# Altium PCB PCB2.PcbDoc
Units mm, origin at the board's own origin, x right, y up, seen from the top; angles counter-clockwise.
Board outline 26.92 x 36.58 mm, 2 copper layers (Top Layer, Bottom Layer); 10 components, 8 nets, 35 pads, 0 vias.
Unrouted connection lines stored in the file: 2.
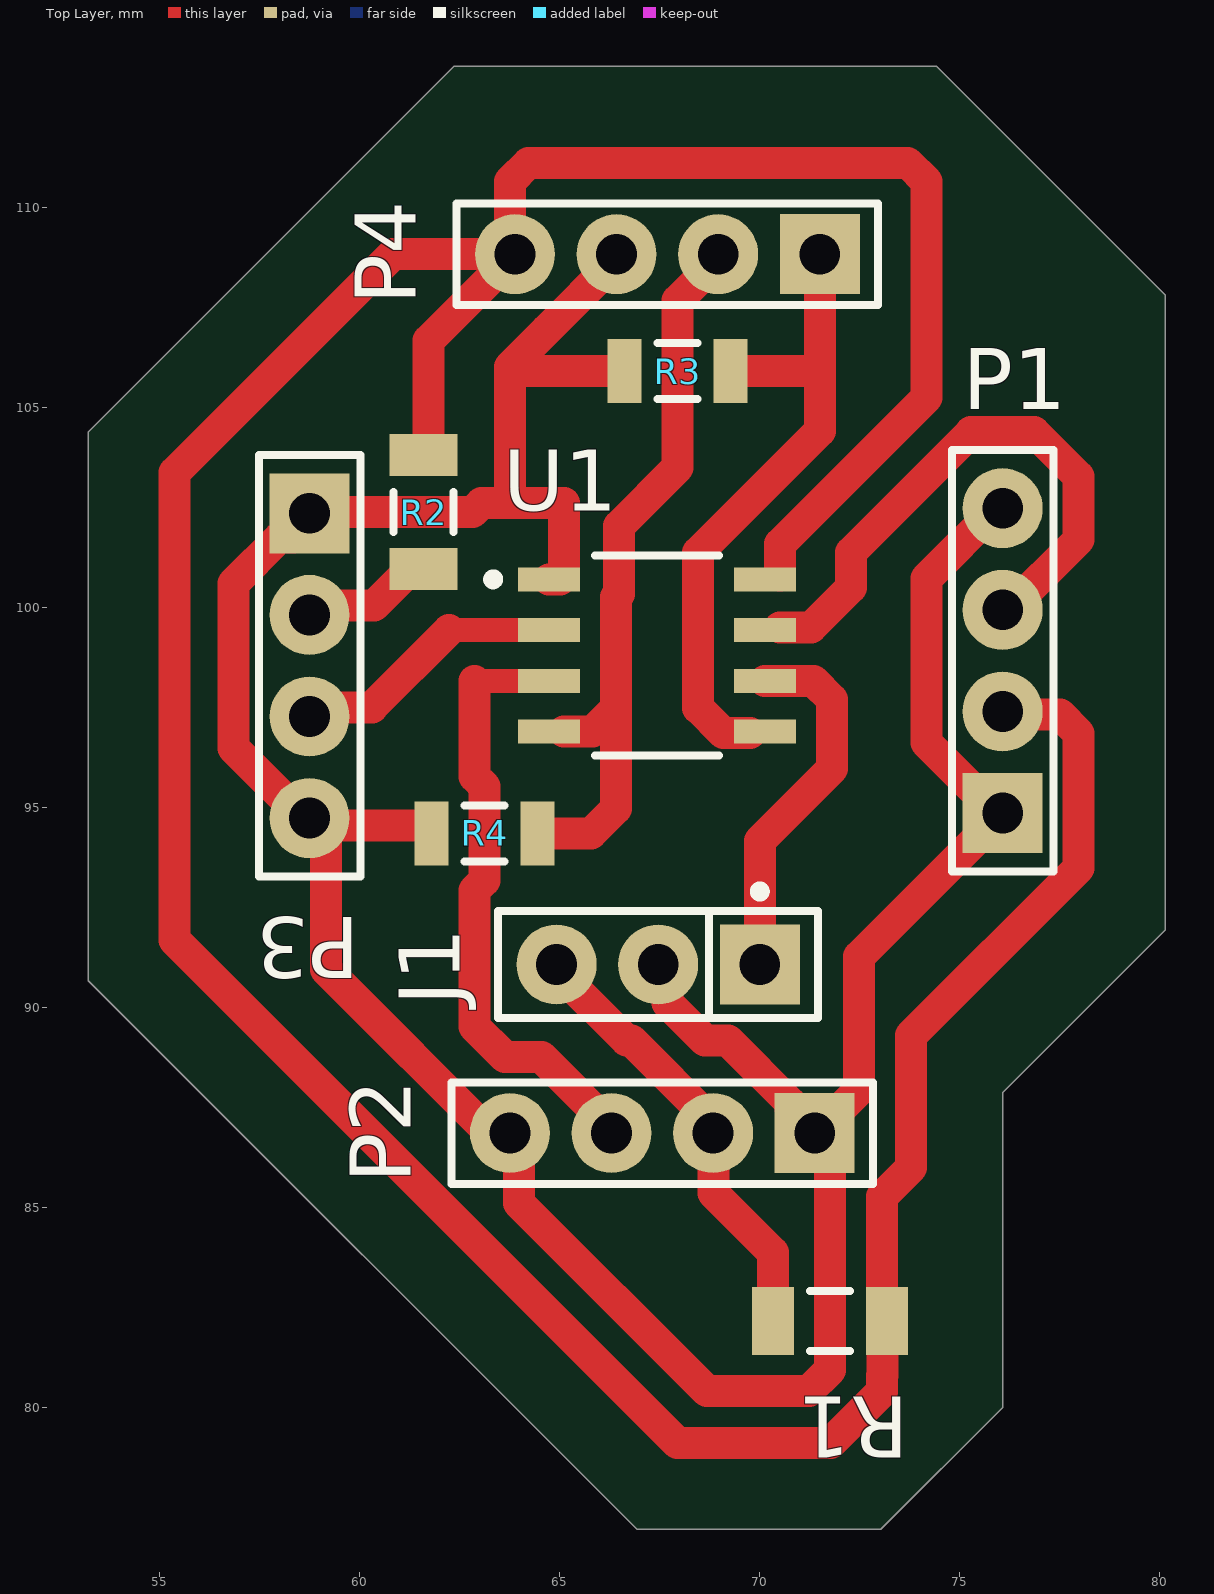
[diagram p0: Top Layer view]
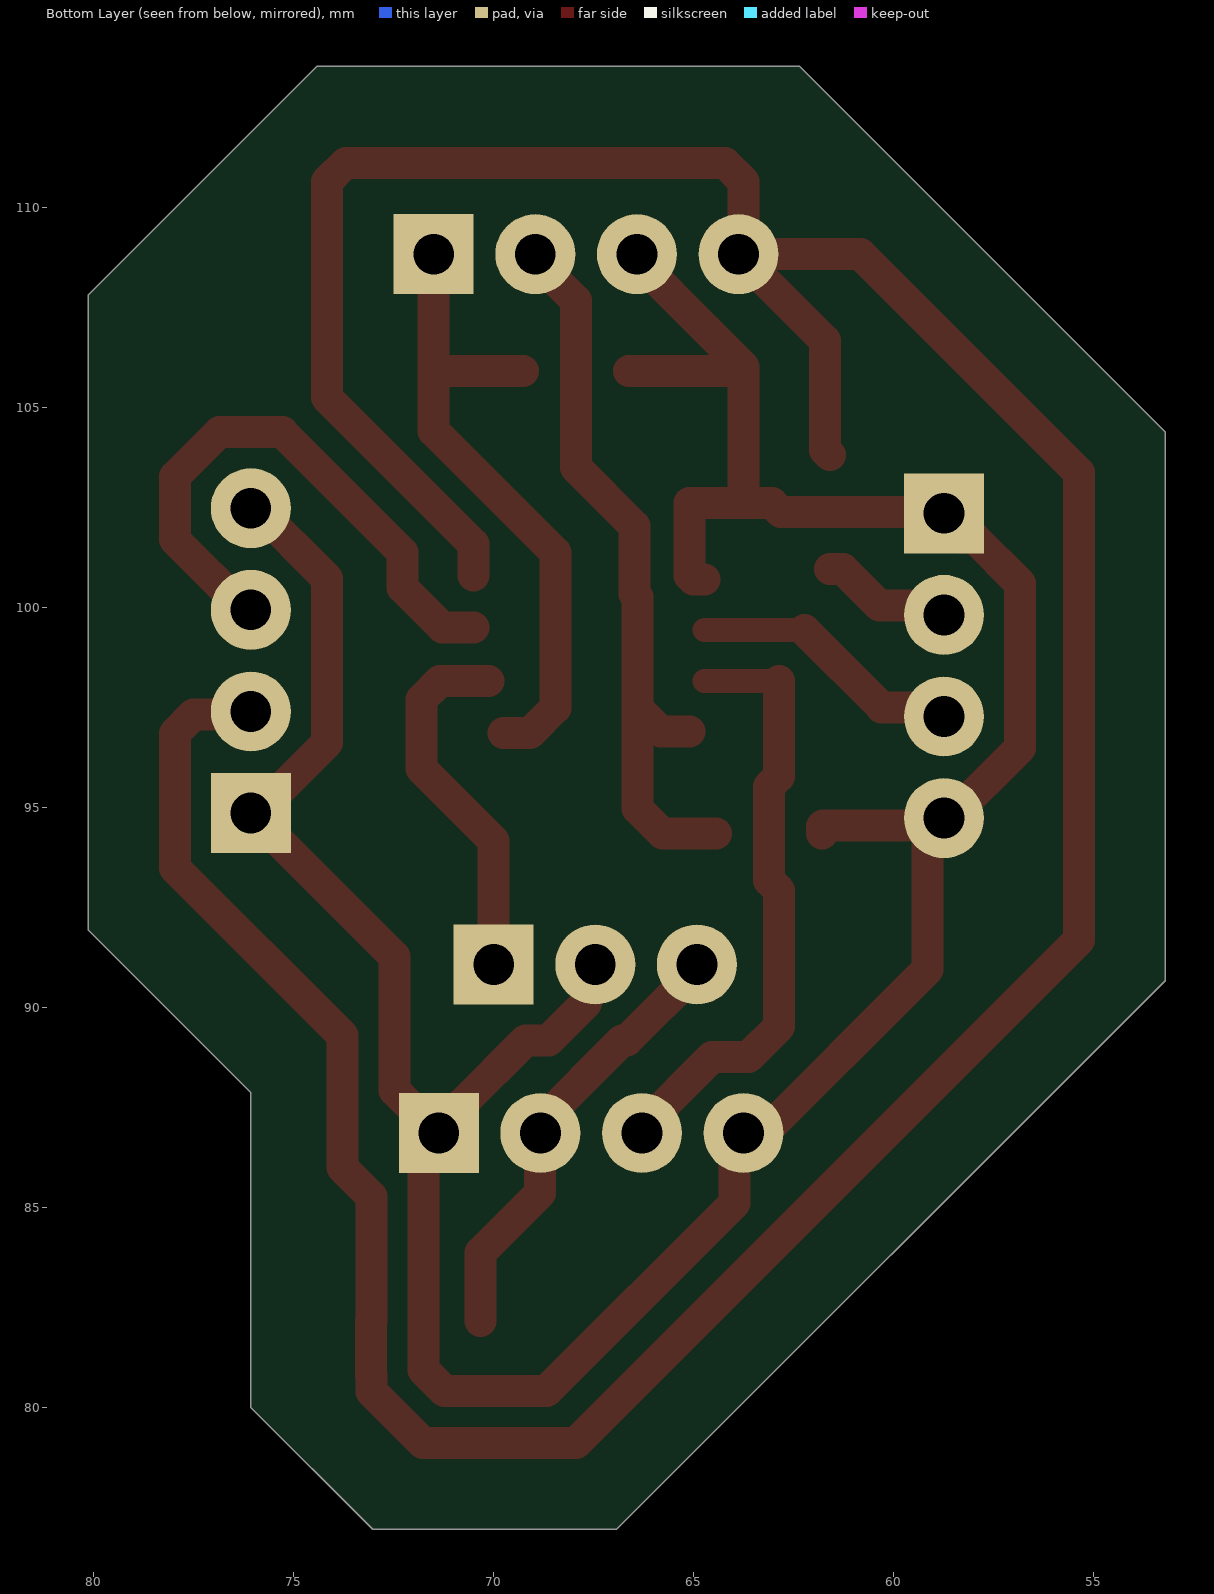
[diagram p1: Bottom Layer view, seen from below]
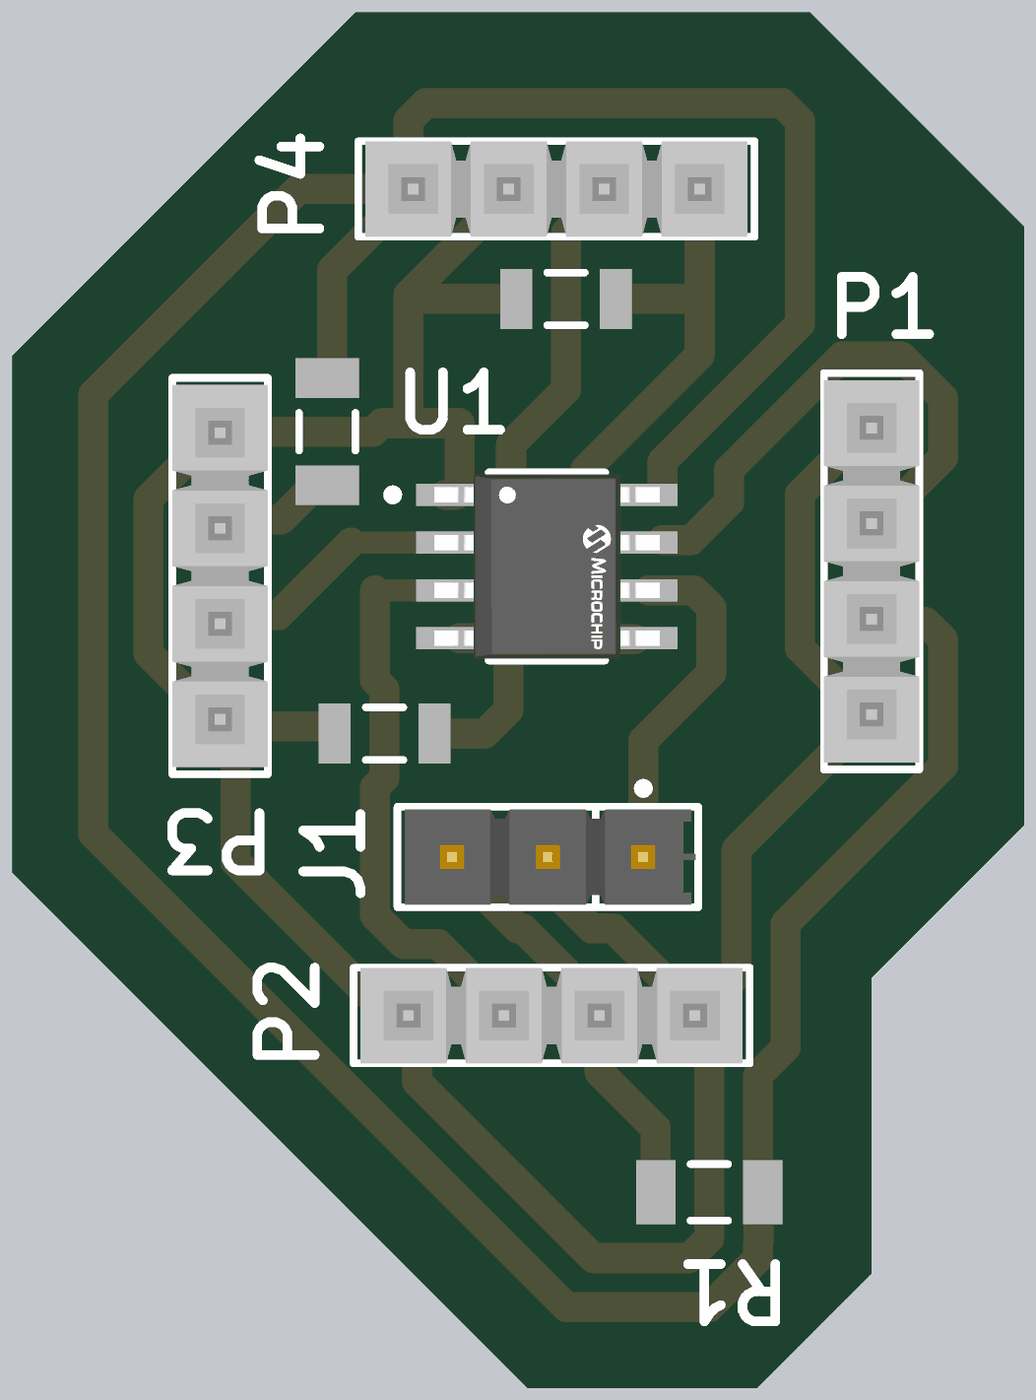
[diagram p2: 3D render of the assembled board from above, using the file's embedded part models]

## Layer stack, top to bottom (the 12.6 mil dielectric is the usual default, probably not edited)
Top Solder: solder mask 0.0102, Solder Resist, Dk 3.5
Top Layer: signal copper 0.0356
Dielectric 1: dielectric 0.32, FR-4, Dk 4.8
Bottom Layer: signal copper 0.0356
Bottom Solder: solder mask 0.0102, Solder Resist, Dk 3.5

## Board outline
66.929,76.962 53.213,90.678 53.213,104.394 62.357,113.538 74.422,113.538 80.137,107.823 80.137,91.948 76.073,87.884 76.073,80.01 73.025,76.962

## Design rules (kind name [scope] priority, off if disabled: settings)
Clearance [All] p1: gap=0.5 ignorepadtopadclearanceinfootprint=FALSE
PolygonConnect [All] p1: connectstyle=Relief reliefconductorwidth=0.254 reliefentries=4 polygonreliefangle="90 Angle" airgapwidth=0.254
RoutingVias [All] p1: holewidth=0.711 width=1.27 viastyle="Through Hole" minholewidth=0.711 minwidth=1.27 maxholewidth=0.711 maxwidth=1.27
SolderMaskExpansion [All] p1: expansion=0 istentingtop=FALSE
SupplyNets "Schematic Supply Nets_1" [InNet('GND')] p1: voltage=0.000
SupplyNets "Schematic Supply Nets" [InNet('VCC3.3')] p2: voltage=0.000
Width [All] p1: maxlimit=0.8 minlimit=0.254 preferedwidth=0.8 toplayer_minwidth=0.6 bottomlayer_maxwidth=0.254 bottomlayer_prefwidth=0.254 minimp=50.000000 maximp=50.000000 favimp=50.000000
30 further rules are at their usual default settings.

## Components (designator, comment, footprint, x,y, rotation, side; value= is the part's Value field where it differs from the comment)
J1 "TSW-103-14-G-S" FP-TSW-103-14-G-S-MFG 67.462,91.082 r180 top
P1 "TSW-104-08-G-S" SMTC-TSW-104-08-X-S 76.073,94.869 r90 top
P2 "TSW-104-08-G-S" SMTC-TSW-104-08-X-S 71.374,86.868 r180 top
P3 "TSW-104-08-G-S" SMTC-TSW-104-08-X-S 58.746,102.362 r270 top
P4 "TSW-104-08-G-S" SMTC-TSW-104-08-X-S 71.501,108.839 r180 top
R1 "RC1206FR-076R98L" RESC3116X65X40NL10T20 71.755,82.169 r180 top
R2 "RC1206FR-076R98L" RESC3116X65X40NL10T20 61.595,102.39 r90 top
R3 "RC1206FR-10750RL" RESC3116X65X40LL10T20 67.945,105.918 r0 top
R4 "RC1206FR-10750RL" RESC3116X65X40LL10T20 63.119,94.361 r0 top
U1 "ATTINY412-SSNR" FP-C04-057-SN-MFG 67.437,98.806 r0 top

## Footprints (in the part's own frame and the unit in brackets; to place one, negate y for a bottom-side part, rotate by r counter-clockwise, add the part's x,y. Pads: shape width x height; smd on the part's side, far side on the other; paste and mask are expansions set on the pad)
FP-C04-057-SN-MFG [mm]
  rect 1.55x0.6 smd paste+0 mask+0: 1(-2.7,1.905) 2(-2.7,0.635) 3(-2.7,-0.635) 4(-2.7,-1.905) 5(2.7,-1.905) 6(2.7,-0.635) 7(2.7,0.635) 8(2.7,1.905)
  silkscreen extent -4.22,-2.5 1.55,2.5, body extent -3.57,-2.75 3.57,2.75, height 0.25
FP-TSW-103-14-G-S-MFG [mm]
  rect 2x2 hole 1.02 paste-2539.97 mask+0: 1(-2.54,0)
  round 2 hole 1.02 paste-2539.97 mask+0: 2(0,0) 3(2.54,0)
  silkscreen extent -4,-1.95 4,1.34, body extent -4.1,-1.44 4.1,1.44, height 0.25
RESC3116X65X40LL10T20 [mm] "Chip Resistor, 2-Leads, Body 3.10x1.60mm, IPC High Density"
  rect 0.85x1.6 smd: 1(-1.325,0) 2(1.325,0)
  silkscreen extent -0.5,-0.7 0.5,0.7, body extent -1.6,-0.85 1.6,0.85, height 0.65
RESC3116X65X40NL10T20 [mm] "Chip Resistor, 2-Leads, Body 3.10x1.60mm, IPC Medium Density"
  rect 1.05x1.7 smd: 1(-1.425,0) 2(1.425,0)
  silkscreen extent -0.5,-0.75 0.5,0.75, body extent -1.6,-0.85 1.6,0.85, height 0.65
SMTC-TSW-104-08-X-S [mm] ".025 SQ Post Terminal Strip Assembly, 1x4 Pins, Vertical, 2.54mm Pitch, Male"
  rect 2x2 hole 1.02: 1(0,0)
  round 2 hole 1.02: 2(2.54,0) 3(5.08,0) 4(7.62,0)
  silkscreen extent -1.46,-1.27 9.08,1.27, body extent -1.27,-1.27 8.89,1.27, height 8.38

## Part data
J1: library part CMP-02766-001743-1, "CONN HEADER VERT 3POS 2.54MM", Color=Black, Flammability Rating="UL94 V-0", Max Current Rating=7.6A, Max Operating Temperature=125°C, Max Voltage Rating (AC)=550V, Min Operating Temperature=-55°C, Package Quantity=1
P1 P2 P3 P4: library part CMP-1024-00357-1, "0.025\" SQ Post Header, Through-hole, Vertical, -55 to 125 degC, 2.54 mm Pitch, 4-Pin, Male, RoHS", Manufacturer=Samtec, Temperature Range="-55 to 125 degC"
R1 R2: library part CMP-2003-03854-1, Manufacturer=Yageo
R3 R4: library part CMP-2003-04964-1, Manufacturer=Yageo
U1: library part CMP-06276-000158-1, "IC MCU 8BIT 4KB FLASH 8SOIC", Case/Package=SOIC, Frequency=20MHz, Max Operating Temperature=105°C, Min Operating Temperature=-40°C

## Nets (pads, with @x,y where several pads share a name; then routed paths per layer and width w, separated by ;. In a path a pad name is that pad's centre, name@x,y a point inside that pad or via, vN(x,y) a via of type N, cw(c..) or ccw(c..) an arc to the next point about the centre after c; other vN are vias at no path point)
GND: J1.3 P1.2 P2.2 P3.2 P4.4 R1.1 R1.2 R2.1 R2.2 U1.8 | length 110.9
  Top Layer w0.8: P3.2 58.975,100.052 60.357,100.052 61.27,100.965 R2.1 ; R2.2 61.72,103.94 61.72,106.678 P4.4 ; J1.3 64.922,90.935 66.675,89.182 66.791,89.182 68.834,87.139 P2.2 ; P2.2@68.842,86.868 68.842,85.365 70.33,83.877 R1.2 ; U1.8@70.512,100.811 70.512,101.595 74.168,105.251 74.168,110.656 73.699,111.125 64.223,111.125 63.754,110.656 63.754,108.839 60.833,108.839 55.372,103.378 55.372,91.694 67.947,79.119 71.766,79.119 73.055,80.408 73.055,80.802 73.065,80.812 73.065,82.159 73.055,82.169 73.055,85.276 73.782,86.003 73.782,89.305 77.973,93.496 77.973,95.118 77.973,96.86 77.504,97.329 76.153,97.329 P1.2
S1: P1.3 U1.7 | length 14.7
  Top Layer w0.8: U1.7@70.512,99.511 U1.7@70.858,99.511 ; U1.7@70.858,99.511 71.285,99.511 72.285,100.511 72.285,101.388 75.286,104.389 76.86,104.389 77.973,103.276 77.973,101.702 76.22,99.949 P1.3
S2: P2.3 U1.3 | length 15.3
  Top Layer w0.6: 62.865,98.171 U1.3
  Top Layer w0.8: 62.865,98.171 62.865,95.788 63.119,95.534 63.119,93.188 62.865,92.934 62.865,89.535 63.632,88.768 64.541,88.768 66.294,87.015 P2.3
S3: P3.3 U1.2 | length 6.7
  Top Layer w0.6: 62.23,99.441 U1.2
  Top Layer w0.8: P3.3@58.928,97.282 59.158,97.512 59.814,97.512 60.301,97.512 62.23,99.441
SCL: P4.1 R3.2 U1.5 | length 16.5
  Top Layer w0.8: R3.2 71.501,105.918 ; U1.5@69.762,96.871 69.089,96.871 68.462,97.498 68.462,101.384 71.501,104.423 71.501,105.918 ; P4.1@71.501,108.931 71.501,105.918
SDA: P4.2 R4.2 U1.4 | length 19.1
  Top Layer w0.8: R4.2 65.786,94.361 66.412,94.987 66.412,97.498 ; U1.4@65.112,96.901 65.815,96.901 66.412,97.498 ; P4.2@69.342,109.073 67.945,107.676 67.945,103.505 66.485,102.045 66.485,100.346 66.412,100.273 66.412,98.844 66.412,97.498
UPDI: J1.1 U1.6 | length 9.2
  Top Layer w0.8: J1.1 70.002,94.173 71.812,95.983 71.812,97.702 71.343,98.171 U1.6
VCC3.3: J1.2 P1.1 P1.4 P2.1 P2.4 P3.1 P3.4 P4.3 R3.1 R4.1 U1.1 | length 84.8
  Top Layer w0.8: P3.4 58.936,94.551 P3.4@59.119,94.551 ; P3.1 58.774,102.39 62.818,102.39 63.044,102.616 63.754,102.616 ; P3.1@58.928,102.362 58.328,101.762 57.999,101.762 56.846,100.609 56.846,96.495 58.599,94.742 58.928,94.742 P3.4@59.119,94.551 ; R4.1 61.794,94.526 61.769,94.551 P3.4@59.119,94.551 ; P2.4@63.5,86.614 59.158,90.956 59.158,94.512 P3.4@59.119,94.551 ; P2.4 63.984,86.638 63.984,85.114 68.679,80.419 71.228,80.419 71.755,80.946 71.755,86.268 71.669,86.354 P2.1@71.536,86.354 ; 63.754,105.918 R3.1 ; U1.1 65.012,100.711 65.112,100.811 65.112,102.616 63.754,102.616 ; P4.3 66.421,108.692 64.668,106.939 63.754,106.025 63.754,102.616 ; J1.2 67.691,90.852 67.691,90.12 68.629,89.182 69.207,89.182 70.774,87.615 70.774,87.468 P2.1 71.974,87.468 72.013,87.468 72.482,87.937 72.482,91.278 P1.1 75.473,95.469 75.326,95.469 74.168,96.627 74.168,100.731 75.926,102.489 P1.4

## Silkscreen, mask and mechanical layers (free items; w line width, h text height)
Mechanical 1:
  the board outline again, w2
